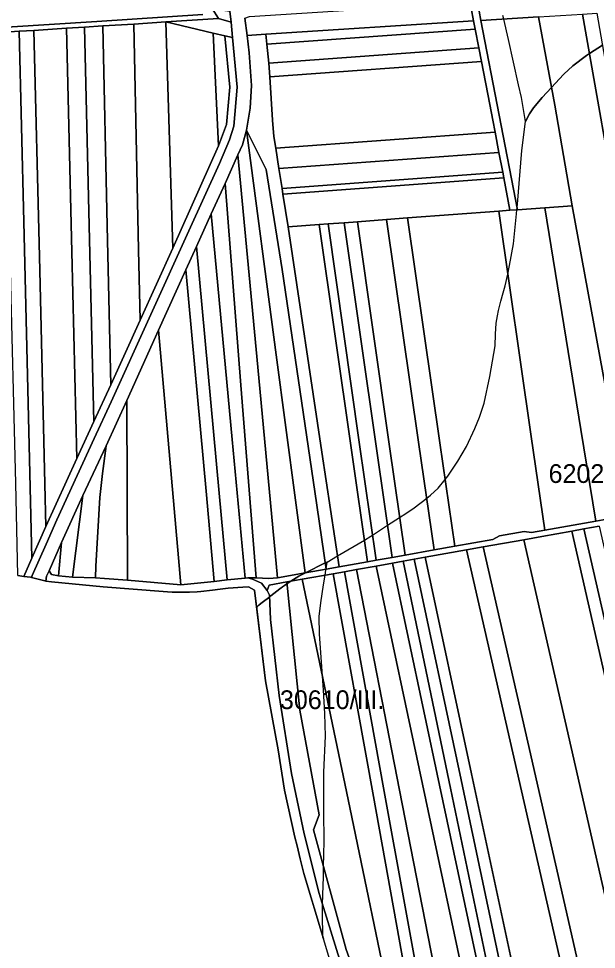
# Model space of a CAD drawing. Extents: x -521939 to -516426, y -1197857 to -1189551.
# Drawn here: x -520145 to -519682, y -1193749 to -1193004 of the extents above; entities that cross this region are included whole.
import ezdxf

# ---------------------------------------------------------------- set-up
doc = ezdxf.new("R2010")
doc.units = 0
for name, color, linetype in [('95560013', 7, 'Continuous'), ('95640013', 7, 'Continuous'), ('95660013', 7, 'Continuous')]:
    doc.layers.add(name, color=color, linetype=linetype)

msp = doc.modelspace()

# ---------------------------------------------------------------- linework, layer by layer
at = {"layer": '95560013'}
for points in [[(-519693.03, -1193000.71), (-519681.4, -1192999.94), (-519650.9, -1193176.49), (-519620.4, -1193353.04), (-519613.26, -1193394.37), (-519623.18, -1193396.11), (-519632.67, -1193342.39), (-519661.73, -1193177.89)], [(-520021.04, -1193188.07), (-520047.22, -1193245.62), (-520048.43, -1193189.33), (-520052.32, -1193008.69), (-520026.61, -1193007.06)], [(-519984.32, -1193106.32), (-520021.04, -1193188.07), (-520026.61, -1193007.06), (-519988.7, -1193015.91)], [(-519779.02, -1193012.78), (-519945.63, -1193024.86), (-519946.52, -1193016.85), (-519780.28, -1193006.26)], [(-519774.46, -1193005.9), (-519728.13, -1193002.94), (-519715.07, -1193073.69), (-519701.27, -1193154.26), (-519723.2, -1193155.82), (-519744.93, -1193157.32)], [(-519728.13, -1193002.94), (-519693.03, -1193000.71), (-519661.73, -1193177.89), (-519632.67, -1193342.39), (-519623.18, -1193396.11), (-519655.8, -1193401.93), (-519668.98, -1193330.14), (-519701.27, -1193154.26), (-519715.07, -1193073.69)], [(-520133.9, -1193436.21), (-520140.41, -1193450.83), (-520145.02, -1193450.27), (-520146.8, -1193376.24), (-520151.14, -1193195.74), (-520155.48, -1193015.24), (-520143.99, -1193014.49), (-520140.34, -1193166.91), (-520136.06, -1193345.78)], [(-520143.99, -1193014.49), (-520132.24, -1193013.75), (-520127.88, -1193194.84), (-520123.5, -1193376.76), (-520122.68, -1193410.82), (-520133.9, -1193436.21), (-520136.06, -1193345.78), (-520140.34, -1193166.91)], [(-520127.88, -1193194.84), (-520132.24, -1193013.75), (-520106.15, -1193012.06), (-520101.83, -1193191.06), (-520097.84, -1193356.45), (-520122.68, -1193410.82), (-520123.5, -1193376.76)], [(-520101.83, -1193191.06), (-520106.15, -1193012.06), (-520091.82, -1193011.2), (-520087.46, -1193192.76), (-520084.24, -1193326.9), (-520097.84, -1193356.45)], [(-520070.77, -1193297.42), (-520084.24, -1193326.9), (-520087.46, -1193192.76), (-520091.82, -1193011.2), (-520077.11, -1193010.24), (-520073.58, -1193170.26)], [(-520047.22, -1193245.62), (-520070.77, -1193297.42), (-520073.58, -1193170.26), (-520077.11, -1193010.24), (-520052.32, -1193008.69), (-520048.43, -1193189.33)], [(-519945.63, -1193024.86), (-519779.02, -1193012.78), (-519776.11, -1193027.69), (-519944.11, -1193039.95)], [(-520122.34, -1193424.94), (-520133.56, -1193450.26), (-520134.2, -1193451.67), (-520134.88, -1193451.49), (-520140.41, -1193450.83), (-520133.9, -1193436.21), (-520122.68, -1193410.82), (-520097.84, -1193356.45), (-520084.24, -1193326.9), (-520070.77, -1193297.42), (-520047.22, -1193245.62), (-520021.04, -1193188.07), (-519984.32, -1193106.32), (-519978.09, -1193089.18), (-519975.45, -1193059.33), (-519979.35, -1193018.09), (-519973.19, -1193019.52), (-519969.42, -1193059.31), (-519972.17, -1193090.33), (-519975.56, -1193101.44), (-519983.64, -1193120.33), (-520008.16, -1193174.24), (-520070.47, -1193311.24), (-520083.91, -1193340.59), (-520097.51, -1193370.06), (-520113.77, -1193405.48)], [(-519988.7, -1193015.91), (-519979.35, -1193018.09), (-519975.45, -1193059.33), (-519978.09, -1193089.18), (-519984.32, -1193106.32)], [(-519944.11, -1193039.95), (-519776.11, -1193027.69), (-519773.98, -1193038.64), (-519943.25, -1193050.97)], [(-519940.04, -1193098.62), (-519941.21, -1193085.76), (-519943.25, -1193050.97), (-519773.98, -1193038.64), (-519767.3, -1193073.15), (-519764.78, -1193085.75), (-519762.98, -1193095.2), (-519938.56, -1193107.97)], [(-519962.06, -1193093.75), (-519938.19, -1193273.62), (-519915.03, -1193448.14), (-519937.09, -1193452.01), (-519952.13, -1193291.96), (-519968.9, -1193113.5), (-519965.3, -1193105.27)], [(-519962.06, -1193093.75), (-519946.35, -1193125.19), (-519933.38, -1193205.21), (-519907.35, -1193382.83), (-519898.22, -1193445.13), (-519915.03, -1193448.14), (-519938.19, -1193273.62)], [(-519936.08, -1193124.31), (-519938.56, -1193107.97), (-519762.98, -1193095.2), (-519759.85, -1193111.45)], [(-519756.74, -1193127.39), (-519933.44, -1193140.29), (-519936.08, -1193124.31), (-519759.85, -1193111.45)], [(-519968.9, -1193113.5), (-519952.13, -1193291.96), (-519937.09, -1193452.01), (-519944.21, -1193452.57), (-519954.39, -1193452.15), (-519966.49, -1193297.87), (-519979.15, -1193136.45)], [(-519755.92, -1193131.74), (-519932.83, -1193144.89), (-519933.44, -1193140.29), (-519756.74, -1193127.39)], [(-519932.83, -1193144.89), (-519755.92, -1193131.74), (-519751.05, -1193157.74), (-519760.07, -1193158.42), (-519833.06, -1193163.91), (-519849.85, -1193165.19), (-519873.26, -1193166.96), (-519883.71, -1193167.74), (-519896.68, -1193168.71), (-519903.79, -1193169.24), (-519928.77, -1193171.13)], [(-519979.15, -1193136.45), (-519966.49, -1193297.87), (-519954.39, -1193452.15), (-519960.89, -1193452.09), (-519963.17, -1193452.22), (-519973.48, -1193341.28), (-519990.26, -1193160.72)], [(-519723.2, -1193155.82), (-519694.28, -1193333.23), (-519682.31, -1193406.66), (-519723.18, -1193413.93), (-519734.03, -1193338.78), (-519760.07, -1193158.42), (-519751.05, -1193157.74), (-519744.93, -1193157.32)], [(-519655.8, -1193401.93), (-519682.31, -1193406.66), (-519694.28, -1193333.23), (-519723.2, -1193155.82), (-519701.27, -1193154.26), (-519668.98, -1193330.14)], [(-519990.26, -1193160.72), (-519973.48, -1193341.28), (-519963.17, -1193452.22), (-519977.51, -1193453.65), (-519983.89, -1193384.34), (-520002.08, -1193186.73)], [(-519795.22, -1193426.76), (-519811.78, -1193429.72), (-519824.21, -1193343.35), (-519849.85, -1193165.19), (-519833.06, -1193163.91), (-519807.15, -1193343.89)], [(-519760.07, -1193158.42), (-519734.03, -1193338.78), (-519723.18, -1193413.93), (-519733.76, -1193415.82), (-519739.68, -1193414.84), (-519759.54, -1193418.38), (-519764.76, -1193421.34), (-519795.22, -1193426.76), (-519807.15, -1193343.89), (-519833.06, -1193163.91)], [(-519928.77, -1193171.13), (-519903.79, -1193169.24), (-519878.18, -1193348.02), (-519865.11, -1193439.26), (-519887.86, -1193443.3), (-519901.66, -1193351.49)], [(-519858.16, -1193437.98), (-519865.11, -1193439.26), (-519878.18, -1193348.02), (-519903.79, -1193169.24), (-519896.68, -1193168.71), (-519871.69, -1193343.4)], [(-519857.82, -1193348.39), (-519845.32, -1193435.61), (-519858.16, -1193437.98), (-519871.69, -1193343.4), (-519896.68, -1193168.71), (-519883.71, -1193167.74)], [(-519873.26, -1193166.96), (-519847.79, -1193344.91), (-519835.06, -1193433.85), (-519845.32, -1193435.61), (-519857.82, -1193348.39), (-519883.71, -1193167.74)], [(-519849.85, -1193165.19), (-519824.21, -1193343.35), (-519811.78, -1193429.72), (-519835.06, -1193433.85), (-519847.79, -1193344.91), (-519873.26, -1193166.96)], [(-520002.08, -1193186.73), (-519983.89, -1193384.34), (-519977.51, -1193453.65), (-519987.87, -1193454.83), (-519994.44, -1193382.67), (-520010.57, -1193205.51)], [(-520010.57, -1193205.51), (-519994.44, -1193382.67), (-519987.87, -1193454.83), (-520014.52, -1193457.55), (-520016.42, -1193435.93), (-520032.44, -1193253.64)], [(-520032.44, -1193253.64), (-520016.42, -1193435.93), (-520014.52, -1193457.55), (-520057.29, -1193454.01), (-520057.96, -1193310.06)], [(-520082.93, -1193451.95), (-520082.6, -1193442.58), (-520079.39, -1193387.67), (-520077.22, -1193368.48), (-520074.37, -1193346.48), (-520057.96, -1193310.06), (-520057.29, -1193454.01), (-520075.67, -1193452.42)], [(-520074.37, -1193346.48), (-520077.22, -1193368.48), (-520079.39, -1193387.67), (-520082.6, -1193442.58), (-520082.93, -1193451.95), (-520101.22, -1193451.41), (-520093.16, -1193385.99)], [(-520093.16, -1193385.99), (-520101.22, -1193451.41), (-520112.52, -1193450.43), (-520110.08, -1193423.75)], [(-519739.99, -1193421.5), (-519725.47, -1193418.95), (-519701.52, -1193414.64), (-519587.75, -1193913.3), (-519609.4, -1193928.24), (-519622.78, -1193935.57)], [(-519701.52, -1193414.64), (-519691.78, -1193412.9), (-519651.6, -1193589.16), (-519612.48, -1193760.77), (-519579.1, -1193907.2), (-519587.75, -1193913.3)], [(-519679.73, -1193410.75), (-519639.39, -1193587.24), (-519598.68, -1193765.35), (-519568.04, -1193899.4), (-519579.1, -1193907.2), (-519612.48, -1193760.77), (-519651.6, -1193589.16), (-519691.78, -1193412.9)], [(-520110.08, -1193423.75), (-520112.52, -1193450.43), (-520118.06, -1193449.48), (-520120.13, -1193446.45)], [(-519652.7, -1193951.75), (-519692.33, -1193778.37), (-519736.87, -1193583.51), (-519772.58, -1193427.28), (-519739.99, -1193421.5), (-519622.78, -1193935.57), (-519633.36, -1193941.29)], [(-519682.62, -1193881.84), (-519709.36, -1193889.56), (-519721.06, -1193893.21), (-519745.1, -1193780.79), (-519781.84, -1193608.98), (-519818.92, -1193435.58), (-519785.8, -1193429.68), (-519745.25, -1193607.38), (-519704.7, -1193785.08)], [(-519652.7, -1193951.75), (-519657.74, -1193954.5), (-519665.13, -1193958.51), (-519682.62, -1193881.84), (-519704.7, -1193785.08), (-519745.25, -1193607.38), (-519785.8, -1193429.68), (-519772.58, -1193427.28), (-519736.87, -1193583.51), (-519692.33, -1193778.37)], [(-519845.18, -1193440.25), (-519836.7, -1193438.75), (-519798.79, -1193620.42), (-519762.71, -1193793.34), (-519740.6, -1193899.3), (-519747.32, -1193901.39), (-519769.7, -1193795.93), (-519807.44, -1193618.09)], [(-519730.3, -1193896.09), (-519735.29, -1193897.65), (-519740.6, -1193899.3), (-519762.71, -1193793.34), (-519798.79, -1193620.42), (-519836.7, -1193438.75), (-519827.72, -1193437.14), (-519790.24, -1193613.71), (-519753.21, -1193788.16)], [(-519818.92, -1193435.58), (-519781.84, -1193608.98), (-519745.1, -1193780.79), (-519721.06, -1193893.21), (-519730.3, -1193896.09), (-519753.21, -1193788.16), (-519790.24, -1193613.71), (-519827.72, -1193437.14)], [(-519892.63, -1193448.74), (-519883.67, -1193447.13), (-519851.71, -1193623.05), (-519819.75, -1193798.97), (-519798.06, -1193918.36), (-519807.25, -1193921.42), (-519828.25, -1193805.16), (-519860.44, -1193626.95)], [(-519873.97, -1193445.38), (-519839.45, -1193621.92), (-519805.28, -1193796.67), (-519782.5, -1193913.17), (-519787.39, -1193914.81), (-519798.06, -1193918.36), (-519819.75, -1193798.97), (-519851.71, -1193623.05), (-519883.67, -1193447.13)], [(-519873.97, -1193445.38), (-519858.21, -1193442.6), (-519821.14, -1193617.12), (-519784.07, -1193791.64), (-519759.87, -1193905.57), (-519762.19, -1193906.35), (-519782.5, -1193913.17), (-519805.28, -1193796.67), (-519839.45, -1193621.92)], [(-519858.21, -1193442.6), (-519845.18, -1193440.25), (-519807.44, -1193618.09), (-519769.7, -1193795.93), (-519747.32, -1193901.39), (-519748.79, -1193901.87), (-519759.87, -1193905.57), (-519784.07, -1193791.64), (-519821.14, -1193617.12)], [(-519917.37, -1193453.09), (-519880.64, -1193629.56), (-519843.45, -1193808.24), (-519819.1, -1193925.23), (-519882.21, -1193749.64), (-519908.38, -1193653.77), (-519903.71, -1193641.87), (-519919.19, -1193557.82), (-519929.74, -1193455.31)], [(-519917.37, -1193453.09), (-519892.63, -1193448.74), (-519860.44, -1193626.95), (-519828.25, -1193805.16), (-519807.25, -1193921.42), (-519819.1, -1193925.23), (-519843.45, -1193808.24), (-519880.64, -1193629.56)]]:
    msp.add_lwpolyline(points, close=True, dxfattribs=at)
at = {"layer": '95640013'}
for points in [[(-520012.68, -1192778.14), (-520003.51, -1192847.12), (-519985.11, -1192985.35), (-519982.68, -1192994.68), (-519979.39, -1192997.86), (-519975.28, -1192998.31), (-519974.42, -1193007.26), (-519984.44, -1193004.38), (-519989.51, -1192996.39), (-519991.05, -1192985.7), (-519991.11, -1192978.26), (-519996.02, -1192941.34), (-520004.11, -1192880.48), (-520009.13, -1192843.07), (-520017.97, -1192840.72), (-520021.35, -1192743.3), (-520021.45, -1192737.96), (-520018.8, -1192697.81), (-520000.53, -1192714.15), (-520004.15, -1192716.76), (-520011.85, -1192728.35), (-520014.48, -1192741.68), (-520013.94, -1192768.6)], [(-519782.25, -1192996.08), (-519780.28, -1193006.26), (-519946.52, -1193016.85), (-519961.59, -1193017.82), (-519963.23, -1193004.02), (-519959.5, -1193002.65), (-519787.9, -1192991.72)], [(-520026.61, -1193007.06), (-519984.44, -1193004.38), (-519974.42, -1193007.26), (-519973.19, -1193019.52), (-519979.35, -1193018.09), (-519988.7, -1193015.91)], [(-519887.86, -1193443.3), (-519898.22, -1193445.13), (-519907.35, -1193382.83), (-519933.38, -1193205.21), (-519946.35, -1193125.19), (-519962.06, -1193093.75), (-519959.22, -1193075.94), (-519957.98, -1193057.97), (-519959.95, -1193031.63), (-519961.59, -1193017.82), (-519946.52, -1193016.85), (-519945.63, -1193024.86), (-519944.11, -1193039.95), (-519943.25, -1193050.97), (-519941.21, -1193085.76), (-519940.04, -1193098.62), (-519938.56, -1193107.97), (-519936.08, -1193124.31), (-519933.44, -1193140.29), (-519932.83, -1193144.89), (-519928.77, -1193171.13), (-519901.66, -1193351.49)], [(-519929.74, -1193455.31), (-519919.19, -1193557.82), (-519903.71, -1193641.87), (-519908.38, -1193653.77), (-519882.21, -1193749.64), (-519819.1, -1193925.23), (-519783.96, -1194017.34), (-519787.2, -1194016.94), (-519793.25, -1194013), (-519797.12, -1194006.88), (-519803, -1193993.09), (-519838.68, -1193893.05), (-519884.16, -1193768.38), (-519903.84, -1193704.77), (-519915.89, -1193656.93), (-519925.96, -1193608.64), (-519935.92, -1193546.31), (-519942.75, -1193485.33), (-519943.72, -1193466.02), (-519945.47, -1193462.14), (-519943.76, -1193457.81)]]:
    msp.add_lwpolyline(points, close=True, dxfattribs=at)
for points in [[(-519777.13, -1192991.04), (-519774.46, -1193005.9), (-519744.93, -1193157.32), (-519751.05, -1193157.74), (-519755.92, -1193131.74), (-519756.74, -1193127.39), (-519759.85, -1193111.45), (-519762.98, -1193095.2), (-519764.78, -1193085.75), (-519767.3, -1193073.15), (-519773.98, -1193038.64), (-519776.11, -1193027.69), (-519779.02, -1193012.78), (-519780.28, -1193006.26), (-519782.25, -1192996.08)], [(-519728.13, -1193002.94), (-519774.46, -1193005.9), (-519777.13, -1192991.04)], [(-519989.51, -1192996.39), (-519984.44, -1193004.38), (-520026.61, -1193007.06), (-520052.32, -1193008.69), (-520077.11, -1193010.24), (-520091.82, -1193011.2), (-520106.15, -1193012.06), (-520132.24, -1193013.75), (-520143.99, -1193014.49), (-520155.48, -1193015.24)], [(-519963.23, -1193004.02), (-519961.59, -1193017.82), (-519959.95, -1193031.63), (-519957.98, -1193057.97), (-519959.22, -1193075.94), (-519962.06, -1193093.75), (-519965.3, -1193105.27), (-519968.9, -1193113.5), (-519979.15, -1193136.45), (-519990.26, -1193160.72), (-520002.08, -1193186.73), (-520010.57, -1193205.51), (-520032.44, -1193253.64), (-520057.96, -1193310.06), (-520074.37, -1193346.48), (-520093.16, -1193385.99), (-520110.08, -1193423.75), (-520120.13, -1193446.45), (-520122.19, -1193450.64), (-520122.83, -1193454.58), (-520123.6, -1193454.5), (-520134.2, -1193451.67), (-520133.56, -1193450.26), (-520122.34, -1193424.94), (-520113.77, -1193405.48), (-520097.51, -1193370.06), (-520083.91, -1193340.59), (-520070.47, -1193311.24), (-520008.16, -1193174.24), (-519983.64, -1193120.33), (-519975.56, -1193101.44), (-519972.17, -1193090.33), (-519969.42, -1193059.31), (-519973.19, -1193019.52), (-519974.42, -1193007.26), (-519975.28, -1192998.31)], [(-519997.12, -1193001.17), (-520081.87, -1193006.54), (-520260.05, -1193017.83), (-520265.83, -1193016.19), (-520285.96, -1193017.47), (-520291.48, -1193019.82), (-520402.9, -1193026.88), (-520578.71, -1193038.02), (-520578.73, -1193042.06), (-520579.51, -1193208.61), (-520579.39, -1193213.66), (-520594.54, -1193214.33), (-520594.51, -1193208.54), (-520594.44, -1193193.51), (-520594.27, -1193157.6), (-520594.19, -1193141.12), (-520594.11, -1193124.54), (-520593.83, -1193063.74), (-520593.65, -1193025.86), (-520593.65, -1193022.39), (-520593.65, -1193003.95)], [(-520260.05, -1193017.83), (-520081.87, -1193006.54), (-519997.12, -1193001.17)], [(-519679.73, -1193410.75), (-519691.78, -1193412.9), (-519701.52, -1193414.64), (-519725.47, -1193418.95), (-519739.99, -1193421.5), (-519772.58, -1193427.28), (-519785.8, -1193429.68), (-519818.92, -1193435.58), (-519827.72, -1193437.14), (-519836.7, -1193438.75), (-519845.18, -1193440.25), (-519858.21, -1193442.6), (-519873.97, -1193445.38), (-519883.67, -1193447.13), (-519892.63, -1193448.74), (-519917.37, -1193453.09), (-519929.74, -1193455.31), (-519943.76, -1193457.81), (-519945.47, -1193462.14), (-519949.89, -1193456.25), (-519957.26, -1193453.06), (-519960.89, -1193452.09), (-519954.39, -1193452.15), (-519944.21, -1193452.57), (-519937.09, -1193452.01), (-519915.03, -1193448.14), (-519898.22, -1193445.13), (-519887.86, -1193443.3), (-519865.11, -1193439.26), (-519858.16, -1193437.98), (-519845.32, -1193435.61), (-519835.06, -1193433.85), (-519811.78, -1193429.72), (-519795.22, -1193426.76), (-519764.76, -1193421.34), (-519759.54, -1193418.38), (-519739.68, -1193414.84), (-519733.76, -1193415.82), (-519723.18, -1193413.93), (-519682.31, -1193406.66), (-519655.8, -1193401.93)], [(-519895.34, -1193757.93), (-519916.08, -1193688.59), (-519919.01, -1193676.86), (-519921.57, -1193666.61), (-519923.3, -1193659.68), (-519931.56, -1193622.07), (-519936.7, -1193589.63), (-519946.78, -1193534.59), (-519955.63, -1193461.89), (-519960.33, -1193459.13), (-519964.98, -1193459.47), (-519976.68, -1193460.34), (-519983.09, -1193461.11), (-519989.19, -1193461.84), (-519998.48, -1193462.95), (-520001.4, -1193463.3), (-520007.58, -1193463.4), (-520021.66, -1193463.62), (-520025.22, -1193463.32), (-520028.77, -1193463.02), (-520076.7, -1193459.13), (-520118.08, -1193455.09), (-520122.83, -1193454.58), (-520122.19, -1193450.64), (-520120.13, -1193446.45), (-520118.06, -1193449.48), (-520112.52, -1193450.43), (-520101.22, -1193451.41), (-520082.93, -1193451.95), (-520075.67, -1193452.42), (-520057.29, -1193454.01), (-520014.52, -1193457.55), (-519987.87, -1193454.83), (-519977.51, -1193453.65), (-519963.17, -1193452.22), (-519960.89, -1193452.09), (-519957.26, -1193453.06), (-519949.89, -1193456.25), (-519945.47, -1193462.14), (-519943.72, -1193466.02), (-519942.75, -1193485.33), (-519935.92, -1193546.31), (-519925.96, -1193608.64), (-519915.89, -1193656.93), (-519903.84, -1193704.77), (-519884.16, -1193768.38)]]:
    msp.add_lwpolyline(points, dxfattribs=at)
at = {"layer": '95660013'}
for points in [[(-519955.63, -1193461.89), (-519953.83, -1193476.71), (-519953.73, -1193476.7), (-519953.84, -1193475.45), (-519952.22, -1193473.99), (-519950.45, -1193472.63), (-519947.27, -1193470.18), (-519943.65, -1193467.4), (-519942.43, -1193466.46), (-519935.23, -1193460.91), (-519933.1, -1193459.31), (-519929.81, -1193456.84), (-519929.6, -1193456.71), (-519926.45, -1193454.72), (-519920.2, -1193450.77), (-519914.89, -1193448.11), (-519898.95, -1193440.14), (-519897.48, -1193439.41), (-519889.18, -1193434.52), (-519867.61, -1193421.8), (-519862.48, -1193418.78), (-519861.04, -1193417.84), (-519849, -1193409.97), (-519839.38, -1193403.68), (-519834.35, -1193400.4), (-519827.7, -1193396.06), (-519817.75, -1193388.24), (-519814.72, -1193385.86), (-519808.58, -1193380.3), (-519802.92, -1193373.3), (-519800.7, -1193370.56), (-519792.81, -1193358.5), (-519785.86, -1193346.91), (-519779.14, -1193332.54), (-519775.43, -1193323.5), (-519771.72, -1193312.14), (-519767.31, -1193290.81), (-519762.91, -1193266.36), (-519762.68, -1193257.08), (-519762.21, -1193248.04), (-519761.01, -1193242.29), (-519760.13, -1193238.07), (-519758.5, -1193230.42), (-519756.48, -1193223.84), (-519754.8, -1193218.37), (-519752.79, -1193208.85), (-519751.32, -1193201.91), (-519748.3, -1193184.52), (-519745.84, -1193160.56), (-519745.51, -1193157.36), (-519745.31, -1193155.39), (-519745.06, -1193152.99), (-519741.58, -1193109.88), (-519738.68, -1193086.69), (-519738.89, -1193085.23), (-519739.84, -1193078.58), (-519741.93, -1193067.45), (-519744.13, -1193057.25), (-519752.25, -1193020.97), (-519756.05, -1193004.72), (-519756.71, -1193001.91)], [(-519676.94, -1193025.74), (-519687.44, -1193032.37), (-519689.77, -1193033.84), (-519700.78, -1193042.18), (-519707.84, -1193048.91), (-519708.08, -1193049.14), (-519717.71, -1193059.41), (-519725.35, -1193067.57), (-519732.19, -1193075.68), (-519735.32, -1193080.67), (-519738.68, -1193086.69), (-519738.89, -1193085.23), (-519739.84, -1193078.58), (-519741.93, -1193067.45), (-519744.13, -1193057.25), (-519752.25, -1193020.97), (-519756.05, -1193004.72), (-519756.71, -1193001.91)], [(-519895.34, -1193757.93), (-519900.39, -1193741.04), (-519900.82, -1193739.6), (-519900.83, -1193738.95), (-519901.19, -1193721.54), (-519901.08, -1193713.7), (-519900.96, -1193705.66), (-519900.5, -1193691.4), (-519900.3, -1193683.37), (-519899.8, -1193663.12), (-519900.03, -1193639.01), (-519900.03, -1193607.48), (-519898.87, -1193578.74), (-519899.1, -1193569.69), (-519899.34, -1193560.65), (-519900.5, -1193541.88), (-519901.27, -1193530.45), (-519903.51, -1193497.13), (-519903.74, -1193482.99), (-519902.58, -1193472.1), (-519900.26, -1193457.72), (-519899.07, -1193449.87), (-519898.47, -1193445.93), (-519898.35, -1193445.15), (-519898.28, -1193444.7), (-519897.48, -1193439.41), (-519889.18, -1193434.52), (-519867.61, -1193421.8), (-519862.48, -1193418.78), (-519861.04, -1193417.84), (-519849, -1193409.97), (-519839.38, -1193403.68), (-519834.35, -1193400.4), (-519827.7, -1193396.06), (-519817.75, -1193388.24), (-519814.72, -1193385.86), (-519808.58, -1193380.3), (-519802.92, -1193373.3), (-519800.7, -1193370.56), (-519792.81, -1193358.5), (-519785.86, -1193346.91), (-519779.14, -1193332.54), (-519775.43, -1193323.5), (-519771.72, -1193312.14), (-519767.31, -1193290.81), (-519762.91, -1193266.36), (-519762.68, -1193257.08), (-519762.21, -1193248.04), (-519761.01, -1193242.29), (-519760.13, -1193238.07), (-519758.5, -1193230.42), (-519756.48, -1193223.84), (-519754.8, -1193218.37), (-519752.79, -1193208.85), (-519751.32, -1193201.91), (-519748.3, -1193184.52), (-519745.84, -1193160.56), (-519745.51, -1193157.36), (-519745.31, -1193155.39), (-519745.06, -1193152.99), (-519741.58, -1193109.88), (-519738.68, -1193086.69), (-519735.32, -1193080.67), (-519732.19, -1193075.68), (-519725.35, -1193067.57), (-519717.71, -1193059.41), (-519708.08, -1193049.14), (-519707.84, -1193048.91), (-519700.78, -1193042.18), (-519689.77, -1193033.84), (-519687.44, -1193032.37), (-519676.94, -1193025.74)], [(-519916.08, -1193688.59), (-519900.39, -1193741.04), (-519900.82, -1193739.6), (-519900.83, -1193738.95), (-519901.19, -1193721.54), (-519901.08, -1193713.7), (-519900.96, -1193705.66), (-519900.5, -1193691.4), (-519900.3, -1193683.37), (-519899.8, -1193663.12), (-519900.03, -1193639.01), (-519900.03, -1193607.48), (-519898.87, -1193578.74), (-519899.1, -1193569.69), (-519899.34, -1193560.65), (-519900.5, -1193541.88), (-519901.27, -1193530.45), (-519902.25, -1193515.89), (-519903.51, -1193497.13), (-519903.74, -1193482.99), (-519902.58, -1193472.1), (-519900.26, -1193457.72), (-519899.07, -1193449.87), (-519898.47, -1193445.93), (-519898.35, -1193445.15), (-519898.28, -1193444.7), (-519897.48, -1193439.41), (-519898.95, -1193440.14), (-519914.89, -1193448.11), (-519920.2, -1193450.77), (-519926.45, -1193454.72), (-519929.6, -1193456.71), (-519929.81, -1193456.84), (-519935.23, -1193460.91), (-519942.43, -1193466.46), (-519943.65, -1193467.4), (-519947.27, -1193470.18), (-519950.45, -1193472.63), (-519952.22, -1193473.99), (-519953.84, -1193475.45), (-519953.73, -1193476.7), (-519953.83, -1193476.71), (-519946.78, -1193534.59), (-519936.7, -1193589.63), (-519931.56, -1193622.07), (-519923.3, -1193659.68), (-519921.57, -1193666.61), (-519919.01, -1193676.86), (-519916.08, -1193688.59)], [(-520145.02, -1193450.27), (-520140.41, -1193450.83), (-520134.88, -1193451.49), (-520134.2, -1193451.67), (-520123.6, -1193454.5), (-520122.83, -1193454.58), (-520118.08, -1193455.09), (-520076.7, -1193459.13), (-520028.77, -1193463.02), (-520025.22, -1193463.32), (-520021.66, -1193463.62), (-520007.58, -1193463.4), (-520001.4, -1193463.3), (-519998.48, -1193462.95), (-519989.19, -1193461.84), (-519983.09, -1193461.11), (-519976.68, -1193460.34), (-519964.98, -1193459.47), (-519960.33, -1193459.13), (-519955.63, -1193461.89)]]:
    msp.add_lwpolyline(points, dxfattribs=at)

# ---------------------------------------------------------------- texts
msp.add_text('62021/IV.', height=15, rotation=360, dxfattribs=at).set_placement((-519720.13, -1193376.06))
msp.add_text('30610/III.', height=15, dxfattribs=at).set_placement((-519935.25, -1193557.08))

doc.saveas('drawing.dxf')
